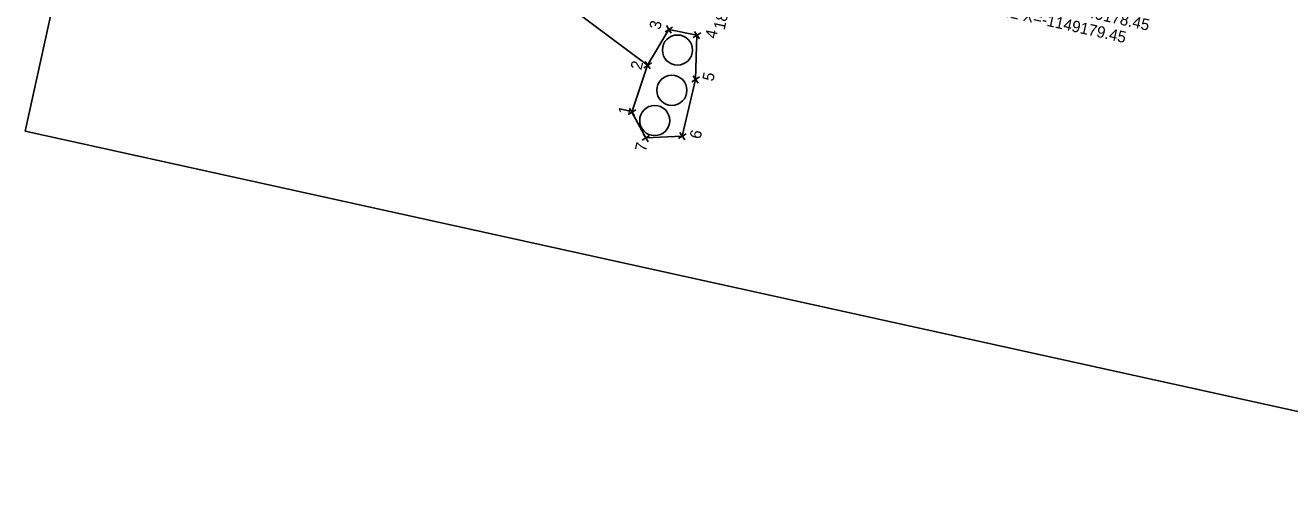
# Model space of a CAD drawing. Extents: x -550960 to -550579, y -1149271 to -1148796.
# Drawn here: x -550959.8 to -550738.3, y -1149270.3 to -1149187.9 of the extents above; entities that cross this region are included whole.
import ezdxf

# ---------------------------------------------------------------- set-up
doc = ezdxf.new("R2010")
doc.units = 0
for name, color, linetype in [('g_bod3', 7, 'Continuous'), ('u_popis', 7, 'Continuous'), ('u_souřadnice1', 7, 'Continuous'), ('u_souřadnice3', 7, 'Continuous'), ('u_vypln_stromy', 7, 'Continuous'), ('u_vysadba', 7, 'Continuous'), ('x_format', 7, 'Continuous')]:
    doc.layers.add(name, color=color, linetype=linetype)

msp = doc.modelspace()

# ---------------------------------------------------------------- linework, layer by layer
at = {"layer": 'g_bod3'}
for p, q in [((-550846.41, -1149188.2), (-550847.73, -1149189.04)), ((-550846.65, -1149189.27), (-550847.49, -1149187.96)), ((-550841.48, -1149189.2), (-550842.8, -1149190.04)), ((-550841.72, -1149190.28), (-550842.56, -1149188.96)), ((-550850.13, -1149194.47), (-550851.45, -1149195.32)), ((-550850.37, -1149195.55), (-550851.21, -1149194.24)), ((-550841.71, -1149196.95), (-550843.02, -1149197.79)), ((-550841.95, -1149198.03), (-550842.79, -1149196.72)), ((-550853.11, -1149203.76), (-550853.96, -1149202.45)), ((-550852.88, -1149202.68), (-550854.19, -1149203.53)), ((-550850.68, -1149208.28), (-550851.52, -1149206.96)), ((-550844.05, -1149206.89), (-550845.37, -1149207.73)), ((-550844.29, -1149207.97), (-550845.13, -1149206.65)), ((-550850.44, -1149207.2), (-550851.76, -1149208.04))]:
    msp.add_line(p, q, dxfattribs=at)
at = {"layer": 'u_popis'}
msp.add_line((-550850.79, -1149194.9), (-550899.96, -1149158.19), dxfattribs=at)
at = {"layer": 'u_vypln_stromy'}
msp.add_lwpolyline([(-550847.07, -1149188.62), (-550850.79, -1149194.9), (-550853.53, -1149203.11), (-550851.1, -1149207.62), (-550844.71, -1149207.31), (-550842.37, -1149197.37), (-550842.14, -1149189.62)], close=True, dxfattribs=at)
msp.add_lwpolyline([(-550847.07, -1149188.62), (-550850.79, -1149194.9), (-550853.53, -1149203.11), (-550851.1, -1149207.62), (-550844.71, -1149207.31), (-550842.37, -1149197.37), (-550842.14, -1149189.62)], close=True, dxfattribs=at)
msp.add_lwpolyline([(-550847.07, -1149188.62), (-550850.79, -1149194.9), (-550853.53, -1149203.11), (-550851.1, -1149207.62), (-550844.71, -1149207.31), (-550842.37, -1149197.37), (-550842.14, -1149189.62)], close=True, dxfattribs=at)
at = {"layer": 'u_vysadba'}
for centre in [(-550845.56, -1149192.24), (-550846.54, -1149199.28), (-550849.54, -1149204.58)]:
    msp.add_circle(centre, 2.64, dxfattribs=at)
at = {"layer": 'x_format'}
msp.add_lwpolyline([(-550579.45, -1148860.11), (-550669.76, -1149270.28), (-550959.82, -1149206.42), (-550869.5, -1148796.24)], close=True, dxfattribs=at)

# ---------------------------------------------------------------- texts
at = {"layer": 'u_souřadnice1'}
for s, p in [('Y=-550803.58 X=-1149178.45', (-550798.24, -1149181.13)), ('Y=-550803.42 X=-1149179.45', (-550802.34, -1149183.28))]:
    msp.add_text(s, height=2, rotation=347.5822, dxfattribs=at).set_placement(p)
at = {"layer": 'u_souřadnice3'}
for s, p in [('3', (-550848.58, -1149188.77)), ('18', (-550837.31, -1149188.82)), ('4', (-550838.79, -1149190.35)), ('2', (-550851.87, -1149195.83)), ('5', (-550839.29, -1149197.82)), ('1', (-550854.04, -1149203.7)), ('6', (-550841.52, -1149207.93)), ('7', (-550851.09, -1149210.12))]:
    msp.add_text(s, height=2, rotation=77.5822, dxfattribs=at).set_placement(p)

doc.saveas('drawing.dxf')
